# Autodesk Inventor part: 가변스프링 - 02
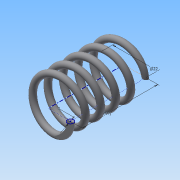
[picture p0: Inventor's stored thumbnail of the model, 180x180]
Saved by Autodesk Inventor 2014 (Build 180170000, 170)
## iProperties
Created: 2015-09
Part Number: 가변스프링 - 02
Material: 강철, 탄소
Document SubType Name: Modeling
Designer: study
Density: 7.87 g/cm^3
Appearance: 반연마
Mass: 18.806 g
Surface Area: 32.4556 cm^2
Volume: 2.38958 cm^3
Author: study
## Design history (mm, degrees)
sketch "스케치1"
  geometry: L1 (0, 0)-(11, 0); L2 (11, 0)-(11, 29.193); L3 (11, 29.193)-(0, 29.193); L4 (0, 29.193)-(0, 0); C1 r 1.5 at (11, 0)
  constraints: 8 end point, 2 parallel, 1 centre point, 1 coincident, 1 horizontal, 1 perpendicular
  dimensions: "d0" = 22 diameter of L2 L4; "d1" = 29.19259 distance of L1.end L2.end (derived); "d2" = 3 diameter of C1
feature "코일1" sketch "스케치1" pitch "d3" = 10; turns "d5" = 5; dims "d4" = 29.19259 (= d1), "d6" = 0, angle "d7" = 90 deg, angle "d8" = 90 deg, "d9" = 0, "d10" = 0
node "작업 평면1"
sketch "스케치2"
  geometry: L1 (-12.5, 0)-(-9.5, 0) reference; 1 further point
  constraints: 1 horizontal alignment
extrude "돌출1" cut sketch "스케치2" stored distance "d12" = 10; taper "d13" = 0 deg
node "작업 평면2"
sketch "스케치3"
  geometry: L1 (-9.5, 0)-(-12.5, 0) reference; 1 further point
  constraints: 1 horizontal alignment
extrude "돌출2" cut sketch "스케치3" stored distance "d15" = 10; taper "d16" = 0 deg
node "솔리드1"
node "절단 모서리 투영1"
node "절단 모서리 투영2"
other parameters: "d11" = 0, "d14" = 29.19259 (= d1)
